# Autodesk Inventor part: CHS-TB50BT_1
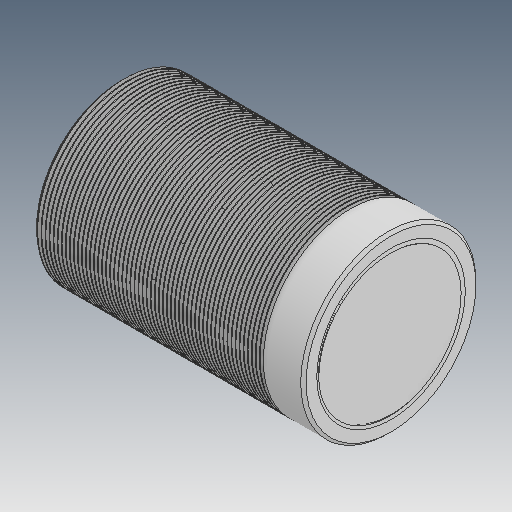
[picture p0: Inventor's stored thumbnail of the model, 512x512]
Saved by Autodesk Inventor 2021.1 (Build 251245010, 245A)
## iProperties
Created: 2019-04
Part Number: CHS-TB50BT_1
Material: Ogólny
Document SubType Name: Modeling
Designer: user
Density: 1 g/cm^3
Appearance: Domyślna
Author: user
Revision Number: ÈÎºÎ
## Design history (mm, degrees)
feature "ÊäÈë1"
feature "ÊäÈë2"
node "Bryła1"
node "Bryła2"
